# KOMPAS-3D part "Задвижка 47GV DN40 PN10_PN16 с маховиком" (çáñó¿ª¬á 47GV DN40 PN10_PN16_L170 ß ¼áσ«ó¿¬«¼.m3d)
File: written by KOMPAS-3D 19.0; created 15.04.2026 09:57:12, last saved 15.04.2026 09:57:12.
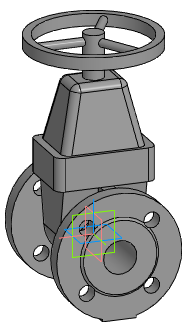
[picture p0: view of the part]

Document properties: Автор: Евгений; Полное имя файла: Z:\3.Личные\kachalov\3d для проектировщиков\2.1 Тип 47GV, 47GV.Z\Задвижка 47GV_DN40-DN600\stp_Задвижка 47GV\Задвижка 47GV DN40 PN10_PN16_L170 с маховиком.m3d

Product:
- Part/product: Задвижка 47GV DN40 PN10_PN16 с маховиком

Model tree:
1. Операция без истории:1  (labels: Задвижка 47GV DN40 PN10_PN16 с маховиком)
